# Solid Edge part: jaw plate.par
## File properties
Title: Jaw Plate
Author: Abhinav
Template: Normal.par
Last saved by: Cadcim
Revision: 8
Application: Solid Edge
Density: 0.0000078 kg/mm^3
Accuracy: 0.01
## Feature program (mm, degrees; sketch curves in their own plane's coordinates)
sketch for "unnamed Protrusion 1" plane through (0, 0, 0) normal (0, -1, 0) x-axis (1, 0, 0)
  line (-34.925, 22.225) -> (34.925, 22.225)
  line (34.925, 22.225) -> (34.925, -22.225)
  line (34.925, -22.225) -> (-34.925, -22.225)
  line (-34.925, -22.225) -> (-34.925, 22.225)
extrude "unnamed Protrusion 1" add finite 4.7498 symmetric
sketch for "Hole_1" plane through (0, -2.3749, 0) normal (0, -1, 0) x-axis (1, 0, 0)
  hole centre (19.05, 3.175) bore radius 3.175
hole "Hole_1" diameter 6.35 through
sketch for "unnamed Hole 1" plane through (0, -2.3749, 0) normal (0, -1, 0) x-axis (1, 0, 0)
  hole centre (-19.05, 3.175) bore radius 3.175
  dimension (linear) = 19.05
  dimension (linear) = 19.05
hole "unnamed Hole 1" through
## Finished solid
Body 1: solid body, 6 faces, 12 edges, 8 vertices.
  Faces by surface: plane 6
  Edges by curve: line 12
Bounding box of the edges (mm): 69.850 x 4.750 x 44.450, from (-34.925, -2.3749, -22.225) to (34.925, 2.3749, 22.225).
Planar faces by outward normal: +x 1, +y 1, +z 1, -x 1, -y 1, -z 1
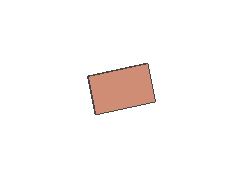
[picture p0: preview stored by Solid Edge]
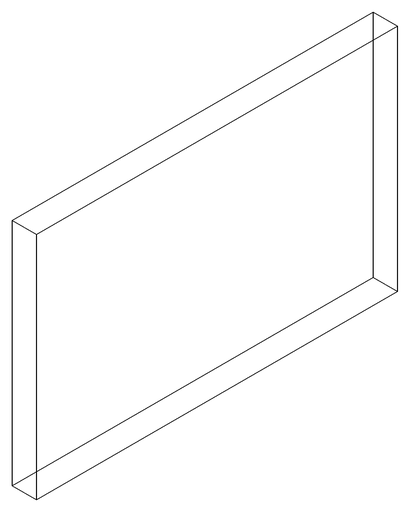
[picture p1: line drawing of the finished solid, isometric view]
